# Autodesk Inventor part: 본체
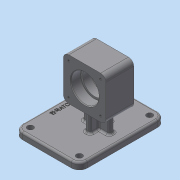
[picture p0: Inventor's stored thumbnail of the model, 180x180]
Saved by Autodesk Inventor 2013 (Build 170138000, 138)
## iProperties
Created: 2020-11
Part Number: 본체
Material: 일반
Document SubType Name: Modeling
Designer: Administrator
Density: 1 g/cm^3
Author: Administrator
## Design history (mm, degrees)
sketch "스케치1"
  geometry: L1 (53, -49)-(-53, -49); L2 (-65, -37)-(-65, 37); L3 (-53, 49)-(53, 49); L4 (65, 37)-(65, -37); L5 (65, -49)-(-65, 49); L6 (-65, -49)-(65, 49); A1 r 12 centre (53, 37) between (65, 37) and (53, 49); A2 r 12 centre (53, -37) between (53, -49) and (65, -37); A3 r 12 centre (-53, -37) between (-65, -37) and (-53, -49); A4 r 12 centre (-53, 37) between (-53, 49) and (-65, 37); 1 further point
  constraints: 12 end point, 8 point on circle, 8 point on line, 8 tangent, 4 centre point, 3 equal radius, 2 midpoint, 2 parallel, 1 horizontal, 1 perpendicular
  dimensions: "d0" = 130 distance of L6.end L5.end; "d2" = 98 distance of L5.start L6.end; "d3" = 12 radius of A1
extrude "돌출1" new body sketch "스케치1" distance "d4" = 10; taper "d5" = 0 deg
node "작업 평면1"
sketch "스케치3"
  geometry: L1 (-21, 19)-(21, 19); L2 (21, 19)-(21, -45); L3 (21, -45)-(-21, -45); L4 (-21, -45)-(-21, 19); L5 (-21, 19)-(21, -45); L6 (21, 19)-(-21, -45); L7 (65, -37)-(65, 37) reference; L8 (53, 49)-(-53, 49) reference; 2 further points
  constraints: 12 end point, 2 midpoint, 2 parallel, 1 horizontal, 1 perpendicular
  dimensions: "d7" = 65 distance from line of point (0, -13) L7; "d9" = 62 distance from line of L8 point (0, -13); "d10" = 42 distance of L1.end L1.start; "d11" = 64 distance of L2.end L1.end
extrude "돌출2" join sketch "스케치3" stored distance "d12" = 64; taper "d13" = 0 deg
fillet "모깎기1" dims "d14" = 8
sketch "스케치4"
  geometry: L1 (65, 37)-(65, -37) reference; L2 (-53, 49)-(53, 49) reference; L3 (-4, 7)-(4, 7); L4 (4, 7)-(4, -33); L5 (4, -33)-(-4, -33); L6 (-4, -33)-(-4, 7); L7 (-4, 7)-(4, -33); L8 (4, 7)-(-4, -33); 1 further point
  constraints: 12 end point, 2 midpoint, 2 parallel, 1 horizontal, 1 perpendicular
  dimensions: "d91" = 65 distance from line of L1 point (0, -13); "d92" = 62 distance from line of point (0, -13) L2; "d93" = 8 distance of L3.end L3.start; "d94" = 40 distance of L5.end L3.start
extrude "돌출3" join sketch "스케치4" stored distance "d20" = 64; taper "d21" = 0 deg
sketch "스케치5"
  geometry: L1 (65, 37)-(65, -37) reference; L2 (-53, 49)-(53, 49) reference; L3 (17, -17)-(-17, -17); L4 (-17, -17)-(-17, -9); L5 (-17, -9)-(17, -9); L6 (17, -9)-(17, -17); L7 (17, -17)-(-17, -9); L8 (-17, -17)-(17, -9); 1 further point
  constraints: 12 end point, 2 midpoint, 2 parallel, 1 horizontal, 1 perpendicular
  dimensions: "d95" = 34 distance of L5.end L4.end; "d97" = 8 distance of L3.end L4.end; "d98" = 65 distance from line of L1 point (0, -13); "d99" = 62 distance from line of L2 point (0, -13)
extrude "돌출4" join sketch "스케치5" stored distance "d27" = 64; taper "d28" = 0 deg
node "작업 평면2"
sketch "스케치6"
  geometry: L1 (0, 0)-(0, 48) reference; L2 (42, 48)-(42, 0) reference; L3 (0, 24)-(42, 24); L4 (0, 45)-(15, 45); L5 (15, 45)-(15, 42); L6 (15, 42)-(27, 42); L7 (27, 42)-(27, 45); L8 (27, 45)-(42, 45); 1 further point
  constraints: 12 end point, 3 horizontal, 3 point on line, 2 midpoint, 2 vertical
  dimensions: "d32" = 42 diameter of L4 L3; "d34" = 15 distance of L4.start L4.end; "d35" = 15 distance of L8.end L7.end; "d36" = 36 diameter of L6 L3
revolve "회전1" sketch "스케치6" stored, may be unused: angle "d37" = 90 deg
fillet "모깎기4" dims "d38" = 3
sketch "스케치7"
  geometry: L1 (-64, 0)-(-64, 48) reference; L2 (-8, -8)-(-56, -8) reference; L3 (0, 48)-(0, 0) reference; L4 (-56, 56)-(-8, 56) reference; C1 r 21 at (-32, 24) reference; A1 r 8 centre (-56, 48) between (-56, 56) and (-64, 48) reference; A2 r 8 centre (-56, 0) between (-64, 0) and (-56, -8) reference; A3 r 8 centre (-8, 0) between (-8, -8) and (0, 0) reference; A4 r 8 centre (-8, 48) between (0, 48) and (-8, 56) reference; 1 further point
hole "구멍1" sketch "스케치7" at (-8, 48), (-8, 0), (-56, 0), (-56, 48) diameter "d39" = 3.242; stored, may be unused: countersink angle "d43" = 90 deg, drill point angle "d45" = 118 deg; dims "d40" = 8, "d41" = 4, "d42" = 2, "d44" = 10
node "작업 평면3"
hole "구멍2" diameter "d49" = 9; stored, may be unused: countersink angle "d53" = 90 deg, drill point angle "d55" = 0 deg; dims "d47" = 10, "d48" = 10, "d50" = 8, "d51" = 4, "d52" = 2, "d54" = 10
hole "구멍3" diameter "d58" = 9; stored, may be unused: countersink angle "d62" = 90 deg, drill point angle "d64" = 0 deg; dims "d56" = 10, "d57" = 10, "d59" = 8, "d60" = 4, "d61" = 2, "d63" = 10
hole "구멍4" diameter "d67" = 9; stored, may be unused: countersink angle "d71" = 90 deg, drill point angle "d73" = 0 deg; dims "d65" = 10, "d66" = 10, "d68" = 8, "d69" = 4, "d70" = 2, "d72" = 10
hole "구멍5" diameter "d76" = 9; stored, may be unused: countersink angle "d80" = 90 deg, drill point angle "d82" = 0 deg; dims "d74" = 10, "d75" = 10, "d77" = 8, "d78" = 4, "d79" = 2, "d81" = 10
sketch "스케치8"
  geometry: L1 (53, 49)-(-53, 49) reference; L2 (65, -37)-(65, 37) reference; 2 further points
  constraints: 1 other
  dimensions: "d83" = 10 distance from line of L1 point (0, 39); "d84" = 65 distance from line of point (0, 39) L2
feature "엠보싱1" sketch "스케치8" dims "d0" = 130, "d2" = 98, "d3" = 12, "d85" = 0.5, "d86" = 0
chamfer "모따기1" distance "d87" = 1; stored, may be unused: second distance "d88" = 2, angle "d89" = 45 deg
fillet "모깎기5" dims "d90" = 0.3
fillet "모깎기6" dims "d100" = 3
fillet "모깎기7" dims "d101" = 3
node "솔리드1"
mirror "대칭1"
node "투영된 루프1"
other parameters: "d31" = -32, "d46" = -21
